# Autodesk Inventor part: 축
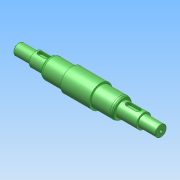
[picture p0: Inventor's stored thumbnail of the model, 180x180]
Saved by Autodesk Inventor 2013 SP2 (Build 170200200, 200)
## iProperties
Created: 2025-08
Part Number: 축
Material: Generic
Document SubType Name: Modeling
Designer: i
Density: 1 g/cm^3
Author: i
변환 표준: STEP AP214IS
전처리기: Build: 200, Release: 2013 SP2 Update 6 - Date: Thu 07/17/2014
전송 단위: 밀리미터
불확실성: 0.01
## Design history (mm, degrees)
node "축1"
node "솔리드1"
node "기준1"
